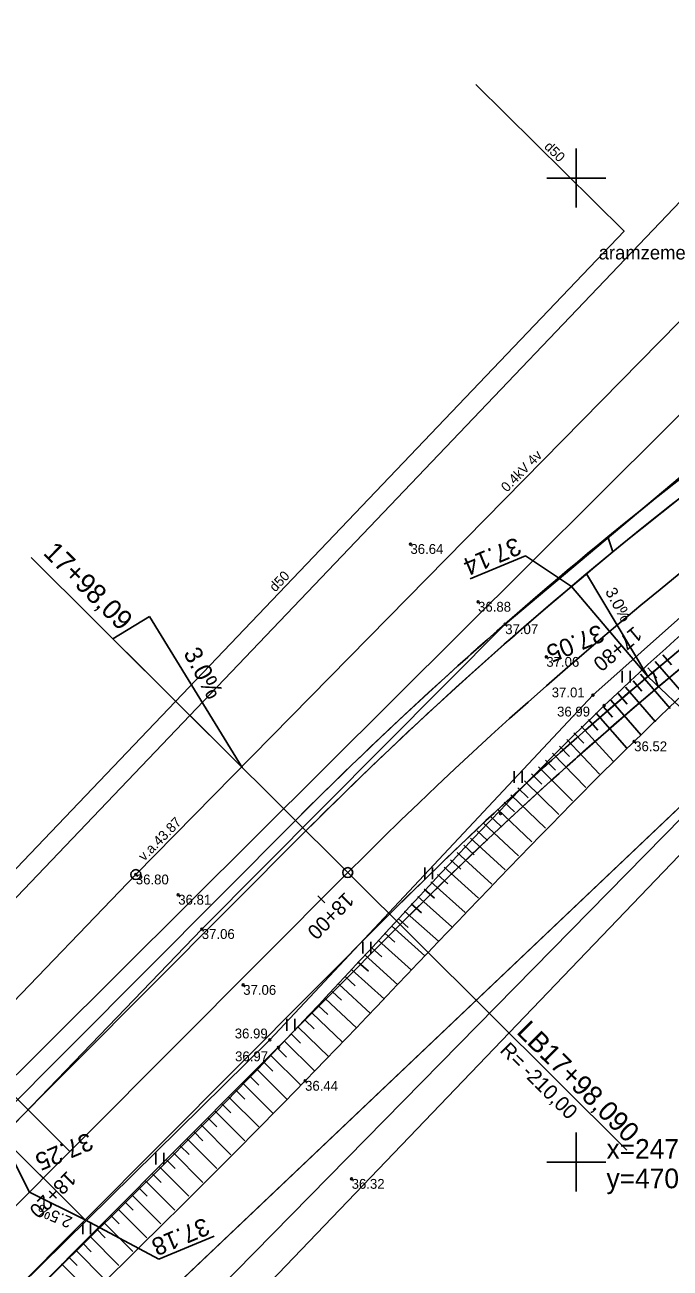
# Model space of a CAD drawing. Extents: x 469981 to 472086, y 246785 to 247785.
# Drawn here: x 470322 to 470354.8, y 247044.6 to 247107.8 of the extents above; entities that cross this region are included whole.
import ezdxf

# ---------------------------------------------------------------- set-up
doc = ezdxf.new("R2010")
doc.units = 0
for name, color, linetype in [('0_922', 7, 'Continuous'), ('0_Asfalta_mala', 7, 'Continuous'), ('0_Asfalta_Nomale', 7, 'Continuous'), ('0_Ruut_Braukt', 7, 'Continuous'), ('0_Ruut_nomale', 7, 'Continuous'), ('0_vertikals', 7, 'Continuous'), ('0_vertkals_cipari', 7, 'Continuous'), ('0_Virazjas', 7, 'Continuous'), ('21', 7, 'Continuous'), ('5_patagas', 7, 'Continuous'), ('6_piketaza', 7, 'Continuous'), ('9', 7, 'Continuous'), ('CELI_CMAL_####_####_#', 7, 'Continuous'), ('DREN_VADP_####_####_#', 7, 'Continuous'), ('DREN_VADP_####_TKST_#', 7, 'Continuous'), ('DREN_VADP_KLKT_####_#', 7, 'Continuous'), ('ELEK_ELEM_####_####_#', 7, 'Continuous'), ('ELEK_VADV_ZSPR_####_#', 7, 'Continuous'), ('ELEK_VADV_ZSPR_TKST_#', 7, 'Continuous'), ('GEOD_ELEM_####_####_#', 7, 'Continuous'), ('GEOD_KORD_####_TKST_#', 7, 'Continuous'), ('RAMI_UZMR_####_####_#', 7, 'Continuous'), ('RELJ_AATZ_####_TKST_#', 7, 'Continuous'), ('RELJ_ELEM_####_####_#', 7, 'Continuous'), ('RELJ_NOGA_####_####_#', 7, 'Continuous'), ('RELJ_NOGL_####_####_#', 7, 'Continuous'), ('ROBZ_IERR_####_####_#', 7, 'Continuous'), ('ROBZ_PROJ_####_####_#', 7, 'Continuous'), ('TERT_ELEM_####_####_#', 7, 'Continuous'), ('TERT_IZMT_####_TKST_#', 7, 'Continuous')]:
    doc.layers.add(name, color=color, linetype=linetype)

msp = doc.modelspace()

# ---------------------------------------------------------------- linework, layer by layer
msp.add_circle((470338.394, 247064.708), 0.25)
at = {"layer": '0_922'}
msp.add_line((470338.394, 247064.708), (470279.553, 247005.63), dxfattribs=at)
msp.add_arc((470487.184, 246916.514), 210, 113.13829, 135.11501, dxfattribs=at)
at = {"layer": '0_Asfalta_mala'}
for p, q in [((470336.269, 247066.825), (470277.427, 247007.747)), ((470340.52, 247062.591), (470281.679, 247003.513))]:
    msp.add_line(p, q, dxfattribs=at)
for radius in [213, 207]:
    msp.add_arc((470487.184, 246916.514), radius, 113.13829, 135.11501, dxfattribs=at)
at = {"layer": '0_Asfalta_Nomale'}
for p, q in [((470335.737, 247067.355), (470276.896, 247008.277)), ((470341.051, 247062.062), (470282.21, 247002.984))]:
    msp.add_line(p, q, dxfattribs=at)
for radius, start in [(206.25, 113.13829), (213.75, 120.08211)]:
    msp.add_arc((470487.184, 246916.514), radius, start, 135.11501, dxfattribs=at)
at = {"layer": '0_Ruut_Braukt'}
for p, q in [((470336.269, 247066.825), (470277.427, 247007.747)), ((470281.679, 247003.513), (470340.52, 247062.591))]:
    msp.add_line(p, q, dxfattribs=at)
for radius in [213, 207]:
    msp.add_arc((470487.184, 246916.514), radius, 113.13829, 135.11501, dxfattribs=at)
at = {"layer": '0_Ruut_nomale'}
for p, q in [((470351.61, 247081.768), (470351.865, 247081.007)), ((470351.865, 247081.007), (470351.61, 247081.768)), ((470353.911, 247074.904), (470354.167, 247074.139)), ((470354.167, 247074.139), (470353.911, 247074.904)), ((470335.737, 247067.355), (470276.896, 247008.277)), ((470277.427, 247007.747), (470336.269, 247066.825)), ((470340.52, 247062.591), (470281.679, 247003.513)), ((470282.21, 247002.984), (470341.051, 247062.062))]:
    msp.add_line(p, q, dxfattribs=at)
for radius, start, end in [(213, 113.13829, 129.44229), (207, 113.13829, 130.0782), (206.25, 113.13829, 130.16049), (213.75, 120.15409, 129.3655), (213.75, 129.3655, 135.11501), (213, 129.44229, 135.11501), (207, 130.0782, 135.11501), (206.25, 130.16049, 135.11501)]:
    msp.add_arc((470487.184, 246916.514), radius, start, end, dxfattribs=at)
at = {"layer": '0_vertikals'}
for p, q in [((470344.619, 247079.633), (470347.429, 247080.809)), ((470349.76, 247079.252), (470347.429, 247080.809)), ((470353.631, 247074.668), (470355.929, 247072.509)), ((470328.79, 247045.063), (470325.058, 247047.067)), ((470328.79, 247045.063), (470331.601, 247046.239))]:
    msp.add_line(p, q, dxfattribs=at)
for points in [[(470353.631, 247074.668), (470350.526, 247079.896), (470349.76, 247079.252)], [(470320.807, 247051.301), (470322.227, 247048.476), (470325.058, 247047.067)]]:
    msp.add_lwpolyline(points, close=True, dxfattribs=at)
at = {"layer": '0_Virazjas'}
for p, q in [((470322.32, 247080.718), (470338.394, 247064.708)), ((470307.99, 247066.763), (470324.28, 247050.538))]:
    msp.add_line(p, q, dxfattribs=at)
msp.add_lwpolyline([(470328.32, 247077.727), (470326.465, 247076.589), (470333.025, 247070.055)], close=True, dxfattribs=at)
at = {"layer": '21'}
msp.add_line((470338.394, 247064.708), (470279.553, 247005.63), dxfattribs=at)
msp.add_arc((470487.184, 246916.514), 210, 113.13829, 135.11501, dxfattribs=at)
at = {"layer": '5_patagas'}
msp.add_lwpolyline([(470338.394, 247064.708), (470352.565, 247050.594)], dxfattribs=at)
at = {"layer": '6_piketaza'}
for points in [[(470351.857, 247076.769), (470351.535, 247077.151)], [(470337.223, 247063.178), (470336.869, 247063.531)], [(470323.11, 247049.008), (470322.755, 247049.361)]]:
    msp.add_lwpolyline(points, dxfattribs=at)
at = {"layer": 'CELI_CMAL_####_####_#'}
for points in [[(470207.251, 246955.004), (470220.145, 246963.116), (470261.486, 246992.424), (470276.308, 247005.858), (470296.122, 247025.635), (470312.816, 247042.969), (470330.98, 247061.836), (470346.394, 247077.324), (470364.172, 247092.272), (470374.754, 247099.764), (470384.938, 247106.322), (470390.015, 247108.873), (470395.699, 247111.348), (470409.875, 247117.262), (470415.428, 247119.375), (470428.615, 247124.712), (470444.307, 247130.298), (470466.241, 247137.389), (470487.751, 247143.859), (470509.15, 247149.677), (470533.329, 247156.368), (470558.982, 247163.161), (470583.723, 247169.81), (470606.354, 247175.581)], [(470440.723, 247107.99), (470440.084, 247118.844), (470439.302, 247119.794), (470438.459, 247120.205), (470437.434, 247120.771), (470435.683, 247121.111), (470417.849, 247114.314), (470398.184, 247106.061), (470376.912, 247095.329), (470368.488, 247089.418), (470350.85, 247073.72), (470334.429, 247056.212), (470317.045, 247039.09), (470299.359, 247021.199), (470279.758, 247002.025), (470265.741, 246988.964), (470242.76, 246971.543), (470223.686, 246958.587), (470209.766, 246949.279)]]:
    msp.add_lwpolyline(points, dxfattribs=at)
at = {"layer": 'DREN_VADP_####_####_#'}
msp.add_lwpolyline([(470344.895, 247104.752), (470352.43, 247097.297), (470267.889, 247008.665), (470215.45, 246973.641)], dxfattribs=at)
at = {"layer": 'DREN_VADP_KLKT_####_#'}
msp.add_lwpolyline([(470355.84, 247029.317), (470356.44, 247045.884), (470357.293, 247069.467), (470322.272, 247033.825), (470311.427, 247022.787), (470278.296, 246989.068), (470265.457, 246976.001), (470248.264, 246964.754), (470217.931, 246944.913)], dxfattribs=at)
at = {"layer": 'ELEK_ELEM_####_####_#'}
for radius in [0.25, 0.0225]:
    msp.add_circle((470327.629, 247064.607), radius, dxfattribs=at)
at = {"layer": 'ELEK_VADV_ZSPR_####_#'}
for q in [(470360.738, 247098.313), (470298.042, 247033.852)]:
    msp.add_line((470327.629, 247064.607), q, dxfattribs=at)
at = {"layer": 'GEOD_ELEM_####_####_#'}
for p, q in [((470350, 247101.5), (470350, 247100)), ((470348.5, 247100), (470350, 247100)), ((470350, 247100), (470350, 247098.5)), ((470350, 247100), (470351.5, 247100)), ((470350, 247051.5), (470350, 247050)), ((470348.5, 247050), (470350, 247050)), ((470350, 247050), (470350, 247048.5)), ((470350, 247050), (470351.5, 247050))]:
    msp.add_line(p, q, dxfattribs=at)
at = {"layer": 'RAMI_UZMR_####_####_#'}
for points in [[(470081.833, 246858.073), (470071.225, 246873.795), (470075.411, 246878.04), (470140.155, 246920.953), (470236.136, 246982.998), (470257.83, 246999.315), (470274.171, 247013.774), (470358.465, 247102.148), (470367.97, 247107.52), (470388.133, 247118.916), (470465.996, 247150.017), (470560.64, 247175.144), (470793.366, 247232.231)], [(470682.857, 247179.693), (470601.924, 247155.957), (470538.749, 247139.954), (470448.7, 247112.965), (470443.256, 247108.572), (470439.042, 247107.166), (470426.399, 247105.409), (470390.93, 247093.141), (470379.516, 247082.95), (470369.859, 247080.841), (470357.567, 247068.014), (470285.914, 246993.254), (470269.057, 246978.845), (470246.406, 246963.908), (470178.978, 246918.441), (470154.395, 246901.045), (470104.604, 246871.942), (470081.833, 246858.073)]]:
    msp.add_lwpolyline(points, dxfattribs=at)
at = {"layer": 'RELJ_ELEM_####_####_#'}
for centre in [(470341.578, 247081.401), (470345.014, 247078.464), (470346.394, 247077.324), (470348.48, 247075.664), (470350.85, 247073.721), (470351.425, 247073.192), (470352.943, 247071.373), (470346.155, 247067.706), (470327.629, 247064.607), (470329.784, 247063.579), (470330.98, 247061.836), (470333.086, 247058.996), (470334.429, 247056.213), (470334.877, 247055.828), (470336.227, 247054.122), (470338.591, 247049.14)]:
    msp.add_circle(centre, 0.05, dxfattribs=at)
at = {"layer": 'RELJ_NOGA_####_####_#'}
for p, q in [((470354.017, 247075.44), (470355.502, 247073.729)), ((470354.395, 247075.768), (470354.837, 247075.258)), ((470353.261, 247074.785), (470354.766, 247073.051)), ((470353.639, 247075.113), (470354.087, 247074.596)), ((470352.506, 247074.13), (470354.03, 247072.374)), ((470352.884, 247074.458), (470353.338, 247073.934)), ((470352.128, 247073.802), (470352.588, 247073.272)), ((470351.373, 247073.147), (470351.84, 247072.611)), ((470351.751, 247073.475), (470353.294, 247071.696)), ((470350.624, 247072.484), (470351.104, 247071.95)), ((470350.997, 247072.817), (470352.576, 247071.033)), ((470349.886, 247071.809), (470350.379, 247071.279)), ((470350.254, 247072.148), (470351.877, 247070.376)), ((470349.158, 247071.124), (470349.66, 247070.598)), ((470349.521, 247071.468), (470351.182, 247069.71)), ((470348.44, 247070.428), (470348.952, 247069.908)), ((470348.798, 247070.777), (470350.49, 247069.035)), ((470347.731, 247069.723), (470348.249, 247069.208)), ((470348.085, 247070.076), (470349.803, 247068.354)), ((470347.38, 247069.367), (470349.117, 247067.665)), ((470346.682, 247068.65), (470348.432, 247066.967)), ((470347.03, 247069.009), (470347.553, 247068.501)), ((470345.992, 247067.927), (470347.749, 247066.263)), ((470346.336, 247068.289), (470346.863, 247067.787)), ((470345.308, 247067.198), (470347.07, 247065.555)), ((470345.649, 247067.563), (470346.177, 247067.067)), ((470344.968, 247066.831), (470345.497, 247066.342)), ((470344.291, 247066.095), (470344.82, 247065.611)), ((470344.629, 247066.463), (470346.394, 247064.844)), ((470343.618, 247065.355), (470344.145, 247064.877)), ((470343.954, 247065.725), (470345.715, 247064.125)), ((470343.283, 247064.984), (470345.038, 247063.403)), ((470342.615, 247064.24), (470344.359, 247062.677)), ((470342.949, 247064.612), (470343.474, 247064.141)), ((470341.948, 247063.495), (470343.68, 247061.948)), ((470342.281, 247063.868), (470342.802, 247063.401)), ((470341.282, 247062.749), (470342.999, 247061.216)), ((470341.615, 247063.122), (470342.132, 247062.66)), ((470340.949, 247062.376), (470341.462, 247061.918)), ((470340.283, 247061.63), (470340.79, 247061.176)), ((470340.616, 247062.003), (470342.317, 247060.484)), ((470339.615, 247060.886), (470340.117, 247060.434)), ((470339.949, 247061.258), (470341.632, 247059.748)), ((470339.281, 247060.514), (470340.943, 247059.011)), ((470338.609, 247059.773), (470340.254, 247058.279)), ((470338.945, 247060.143), (470339.442, 247059.694)), ((470337.934, 247059.035), (470339.555, 247057.54)), ((470338.272, 247059.404), (470338.762, 247058.955)), ((470337.595, 247058.668), (470338.079, 247058.22)), ((470336.913, 247057.937), (470337.39, 247057.488)), ((470337.254, 247058.302), (470338.855, 247056.806)), ((470336.225, 247057.211), (470336.696, 247056.761)), ((470336.569, 247057.573), (470338.149, 247056.073)), ((470335.53, 247056.491), (470335.995, 247056.038)), ((470335.878, 247056.85), (470337.437, 247055.342)), ((470335.18, 247056.134), (470336.723, 247054.618)), ((470334.475, 247055.425), (470336.005, 247053.901)), ((470334.828, 247055.779), (470335.288, 247055.322)), ((470333.769, 247054.717), (470335.295, 247053.194)), ((470334.123, 247055.071), (470334.581, 247054.614)), ((470333.063, 247054.009), (470334.584, 247052.488)), ((470333.416, 247054.363), (470333.873, 247053.907)), ((470332.356, 247053.302), (470333.874, 247051.783)), ((470332.709, 247053.655), (470333.165, 247053.2)), ((470332.002, 247052.949), (470332.457, 247052.493)), ((470331.294, 247052.242), (470331.748, 247051.787)), ((470331.648, 247052.595), (470333.163, 247051.077)), ((470330.586, 247051.536), (470331.039, 247051.081)), ((470330.94, 247051.889), (470332.453, 247050.373)), ((470329.878, 247050.83), (470330.33, 247050.376)), ((470330.232, 247051.183), (470331.741, 247049.668)), ((470329.169, 247050.125), (470329.621, 247049.671)), ((470329.523, 247050.477), (470331.03, 247048.964)), ((470328.815, 247049.772), (470330.319, 247048.26)), ((470328.106, 247049.067), (470329.609, 247047.556)), ((470328.46, 247049.419), (470328.911, 247048.966)), ((470327.397, 247048.361), (470328.898, 247046.853)), ((470327.751, 247048.714), (470328.202, 247048.261)), ((470326.688, 247047.656), (470328.188, 247046.149)), ((470327.043, 247048.008), (470327.493, 247047.556)), ((470326.334, 247047.303), (470326.783, 247046.851)), ((470325.625, 247046.598), (470326.074, 247046.146)), ((470325.979, 247046.95), (470327.477, 247045.446)), ((470324.917, 247045.892), (470325.365, 247045.442)), ((470325.271, 247046.245), (470326.767, 247044.743)), ((470324.208, 247045.186), (470324.656, 247044.736)), ((470324.562, 247045.539), (470326.057, 247044.039)), ((470323.854, 247044.833), (470325.348, 247043.336))]:
    msp.add_line(p, q, dxfattribs=at)
msp.add_spline([(470120.845, 246890.769), (470123.591, 246892.466), (470150.351, 246909.177), (470171.26, 246922.106), (470191.149, 246935.734), (470210.204, 246948.514), (470224.202, 246958.074), (470243.113, 246970.411), (470266.522, 246987.913), (470280.536, 247001.251), (470299.823, 247020.383), (470317.592, 247038.544), (470334.877, 247055.828), (470351.425, 247073.192), (470366.151, 247085.967)], degree=3, dxfattribs=at)
at = {"layer": 'RELJ_NOGL_####_####_#'}
msp.add_spline([(470122.047, 246889.925), (470124.645, 246891.606), (470151.263, 246908.028), (470171.623, 246921.498), (470191.873, 246934.822), (470224.882, 246957.282), (470243.432, 246969.856), (470267.182, 246986.981), (470282.015, 246999.84), (470300.677, 247018.663), (470318.825, 247036.845), (470336.227, 247054.122), (470352.943, 247071.373), (470367.141, 247084.447)], degree=3, dxfattribs=at)
at = {"layer": 'ROBZ_IERR_####_####_#'}
for points in [[(470310.127, 246974.356), (470275.956, 246992.729), (470371.503, 247083.47), (470396.219, 247097.502), (470431.624, 247112.202), (470468.364, 247124.23), (470636.973, 247175.147), (470640.03, 247134.708)], [(470335.002, 247137.782), (470368.265, 247098.262), (470361.554, 247094.257), (470278.124, 247011.202), (470269.149, 247002.795), (470222.435, 247031.786)]]:
    msp.add_lwpolyline(points, dxfattribs=at)
at = {"layer": 'ROBZ_PROJ_####_####_#'}
for points in [[(471398.351, 247372.094), (471346.741, 247338.478), (471133.176, 247205.05), (471108.425, 247194.786), (471087.339, 247189.709), (471023.306, 247181.157), (470962.604, 247185.245), (470905.63, 247205.857), (470878.75, 247214.454), (470852.344, 247217.039), (470815.743, 247215.147), (470778.583, 247209.26), (470718.669, 247194.633), (470636.973, 247175.147), (470468.364, 247124.23), (470431.624, 247112.202), (470396.219, 247097.502), (470371.503, 247083.47), (470275.956, 246992.729), (470152.342, 246907.761), (470066.737, 246851.23)], [(470062.774, 246863.479), (470070.591, 246868.587), (470253.618, 246988.247), (470269.149, 247002.795), (470278.124, 247011.202), (470361.554, 247094.257), (470368.265, 247098.262), (470383.103, 247107.116), (470421.395, 247122.632), (470438.432, 247129.536), (470474.818, 247141.882), (470613.752, 247179.765), (470688.303, 247197.106)]]:
    msp.add_lwpolyline(points, dxfattribs=at)
at = {"layer": 'TERT_ELEM_####_####_#'}
for p, q in [((470352.339, 247074.361), (470352.339, 247074.961)), ((470352.739, 247074.361), (470352.739, 247074.961)), ((470346.855, 247069.265), (470346.855, 247069.865)), ((470347.255, 247069.265), (470347.255, 247069.865)), ((470342.301, 247064.365), (470342.301, 247064.965)), ((470342.701, 247064.365), (470342.701, 247064.965)), ((470339.167, 247060.591), (470339.167, 247061.191)), ((470339.567, 247060.591), (470339.567, 247061.191)), ((470335.299, 247056.671), (470335.299, 247057.271)), ((470335.699, 247056.671), (470335.699, 247057.271)), ((470328.651, 247049.87), (470328.651, 247050.47)), ((470329.051, 247049.87), (470329.051, 247050.47)), ((470324.93, 247046.342), (470324.93, 247046.942)), ((470325.33, 247046.342), (470325.33, 247046.942))]:
    msp.add_line(p, q, dxfattribs=at)

# ---------------------------------------------------------------- texts
msp.add_text('R= -210,00', height=0.75, rotation=315.11501).set_placement((470346.075, 247055.629))
at = {"layer": '0_vertkals_cipari'}
for s, height, rotation, p in [('37.14', 0.9, 202.71113, (470346.953, 247081.766)), ('3.0%', 0.5993, 298.32014, (470351.452, 247078.991)), ('37.05', 0.9, 202.71113, (470351.177, 247077.343)), ('37.25', 0.9, 202.71113, (470325.211, 247051.52)), ('2.5%', 0.5993, 157.17681, (470324.452, 247047.168)), ('37.18', 0.9, 202.71113, (470331.124, 247047.196))]:
    msp.add_text(s, height=height, rotation=rotation, dxfattribs=at).set_placement(p)
at = {"layer": '0_Virazjas'}
for s, height, rotation, p in [('17+98,09', 1, 315.11501, (470322.874, 247080.907)), ('3.0%', 0.899, 297.99318, (470330.029, 247075.855))]:
    msp.add_text(s, height=height, rotation=rotation, dxfattribs=at).set_placement(p)
at = {"layer": '6_piketaza'}
for s, rotation, p in [('17+80', 220.17941, (470352.946, 247077.263)), ('18+00', 225.11501, (470338.266, 247063.765)), ('18+20', 225.11501, (470324.152, 247049.594))]:
    msp.add_text(s, height=0.75, rotation=rotation, dxfattribs=at).set_placement(p)
at = {"layer": '9'}
msp.add_text('LB17+98,090', height=1, rotation=315.11501, dxfattribs=at).set_placement((470346.926, 247056.564))
at = {"layer": 'DREN_VADP_####_TKST_#'}
for rotation, p in [(315.30329, (470348.338, 247101.556)), (46.35329, (470334.711, 247078.937))]:
    msp.add_text('d50', height=0.5, rotation=rotation, dxfattribs=at).set_placement(p)
at = {"layer": 'ELEK_VADV_ZSPR_TKST_#'}
for s, p in [('0.4kV 4v', (470346.48, 247084.011)), ('v.a.43.87', (470328.057, 247065.257))]:
    msp.add_text(s, height=0.5, rotation=45.51219, dxfattribs=at).set_placement(p)
at = {"layer": 'GEOD_KORD_####_TKST_#'}
for s, p in [('x=247050', (470351.539, 247050.166)), ('y=470350', (470351.539, 247048.666))]:
    msp.add_text(s, height=1, dxfattribs=at).set_placement(p)
at = {"layer": 'RELJ_AATZ_####_TKST_#'}
for s, p in [('36.64', (470341.578, 247080.901)), ('36.88', (470345.014, 247077.964)), ('37.07', (470346.394, 247076.824)), ('37.06', (470348.48, 247075.164)), ('37.01', (470348.755, 247073.611)), ('36.99', (470349.027, 247072.639)), ('36.52', (470352.943, 247070.873)), ('36.80', (470327.629, 247064.107)), ('36.81', (470329.784, 247063.079)), ('37.06', (470330.98, 247061.336)), ('37.06', (470333.085, 247058.496)), ('36.99', (470332.654, 247056.281)), ('36.97', (470332.671, 247055.12)), ('36.44', (470336.227, 247053.622)), ('36.32', (470338.591, 247048.64))]:
    msp.add_text(s, height=0.5, dxfattribs=at).set_placement(p)
at = {"layer": 'TERT_IZMT_####_TKST_#'}
msp.add_text('aramzeme', height=0.7, dxfattribs=at).set_placement((470351.139, 247095.863))

doc.saveas('drawing.dxf')
